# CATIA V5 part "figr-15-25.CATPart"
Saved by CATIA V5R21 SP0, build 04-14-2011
Part number: Part1
Bounding box of the stored display mesh (mm): x -50 to 50, y -25 to 26, z -24 to 1
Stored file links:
  D:\CATIA V5R21 E-RESOURCES\CATIA-V5R21\catia-v5r21-prt\c15-catia-v5r20-prt\c15-catia-v5r21-figr-15-25.CATPart
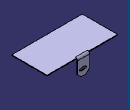
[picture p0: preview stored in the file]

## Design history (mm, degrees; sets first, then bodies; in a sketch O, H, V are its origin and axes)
SheetMetalParameters1: Thickness 1, BendRadius 2, KFactor 0.400515 {= log(min(100,max(20*SheetMetalParameters1.BendRadius,SheetMetalParameters1.Thickness)/SheetMetalParameters1.Thickness))/log(100)/2}, ReliefRadialLength 1, ReliefAxialLength 2, MinimumBendRadius 0
Body1 (main body)
  Sketch1 on xy-plane, origin (0, 0, 0), H (1, 0, 0), V (0, 1, 0)
    line L1 (-50, 25) -> (50, 25)
    line L2 (50, 25) -> (50, -25)
    line L3 (50, -25) -> (-50, -25)
    line L4 (-50, -25) -> (-50, 25)
    length L1 = 100
    distance V L2 = 50
    length L2 = 50
    distance H L3 = 25
    horizontal: L1 H, L3 H
    vertical: L2 V, L4 V
  Wall1: Thickness 1, Profile Sketch1
  Sketch2 on face of Wall1, origin (50, 25, 0), H (-1, 0, 0), V (0, 0, 1)
    line L1 (42.3549, 1) -> (42.3549, -19)
    point P2 (42.3549, -19)
    line L2 (42.3549, -19) -> (47.3549, -24)
    point P3 (47.3549, -24)
    line L3 (47.3549, -24) -> (54.3549, -24)
    point P4 (54.3549, -24)
    line L4 (54.3549, -24) -> (59.3549, -19)
    point P5 (59.3549, -19)
    line L5 (59.3549, -19) -> (59.3549, 1)
    line L6 (59.3549, 1) -> (42.3549, 1)
    reference projected line E1 (100, 1) -> (0, 1) from edge [face of Wall1 | face of Wall1]
    ellipse A1 centre (50.1164, -15.2153) semi-axes 5.0583, 2.1402 rotation 0
    length L5 = 20
    length L1 = 20
    length L3 = 7
    distance P4 L5 = 5
    distance P2 P3 H = 5
    distance L3 P5 = 5
    vertical: L1 V, L5 V
    horizontal: L3 H, L6 H
    coincidence: L6 E1
    parallelism: A1 L3
  d_NewWallOnEdge1: NewWallOnEdge_Edge edge [face of Wall1 | face of Wall1], NewWallOnEdge_WallProfile Sketch2, NewWallOnEdge_Length 100, NewWallOnEdge_HeightLimitOffset 0, NewWallOnEdge_WidthOffset1 0, NewWallOnEdge_WidthOffset2 0, NewWallOnEdge_Angle 0, NewWallOnEdge_BendRadiusValue 2 {= SheetMetalParameters1.BendRadius}, NewWallOnEdge_BendTable SheetMetalParameters1, KFacteur 0.400515 {= log(min(100,max(20*d_NewWallOnEdge1.Radius,SheetMetalParameters1.Thickness)/SheetMetalParameters1.Thickness))/log(100)/2}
